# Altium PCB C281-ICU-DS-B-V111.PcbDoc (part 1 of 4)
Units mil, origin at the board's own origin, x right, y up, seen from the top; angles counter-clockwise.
Board outline 9370.03 x 5995.03 mil, 2 copper layers (Top Layer, Bottom Layer); 468 components, 321 nets, 1241 pads, 808 vias.
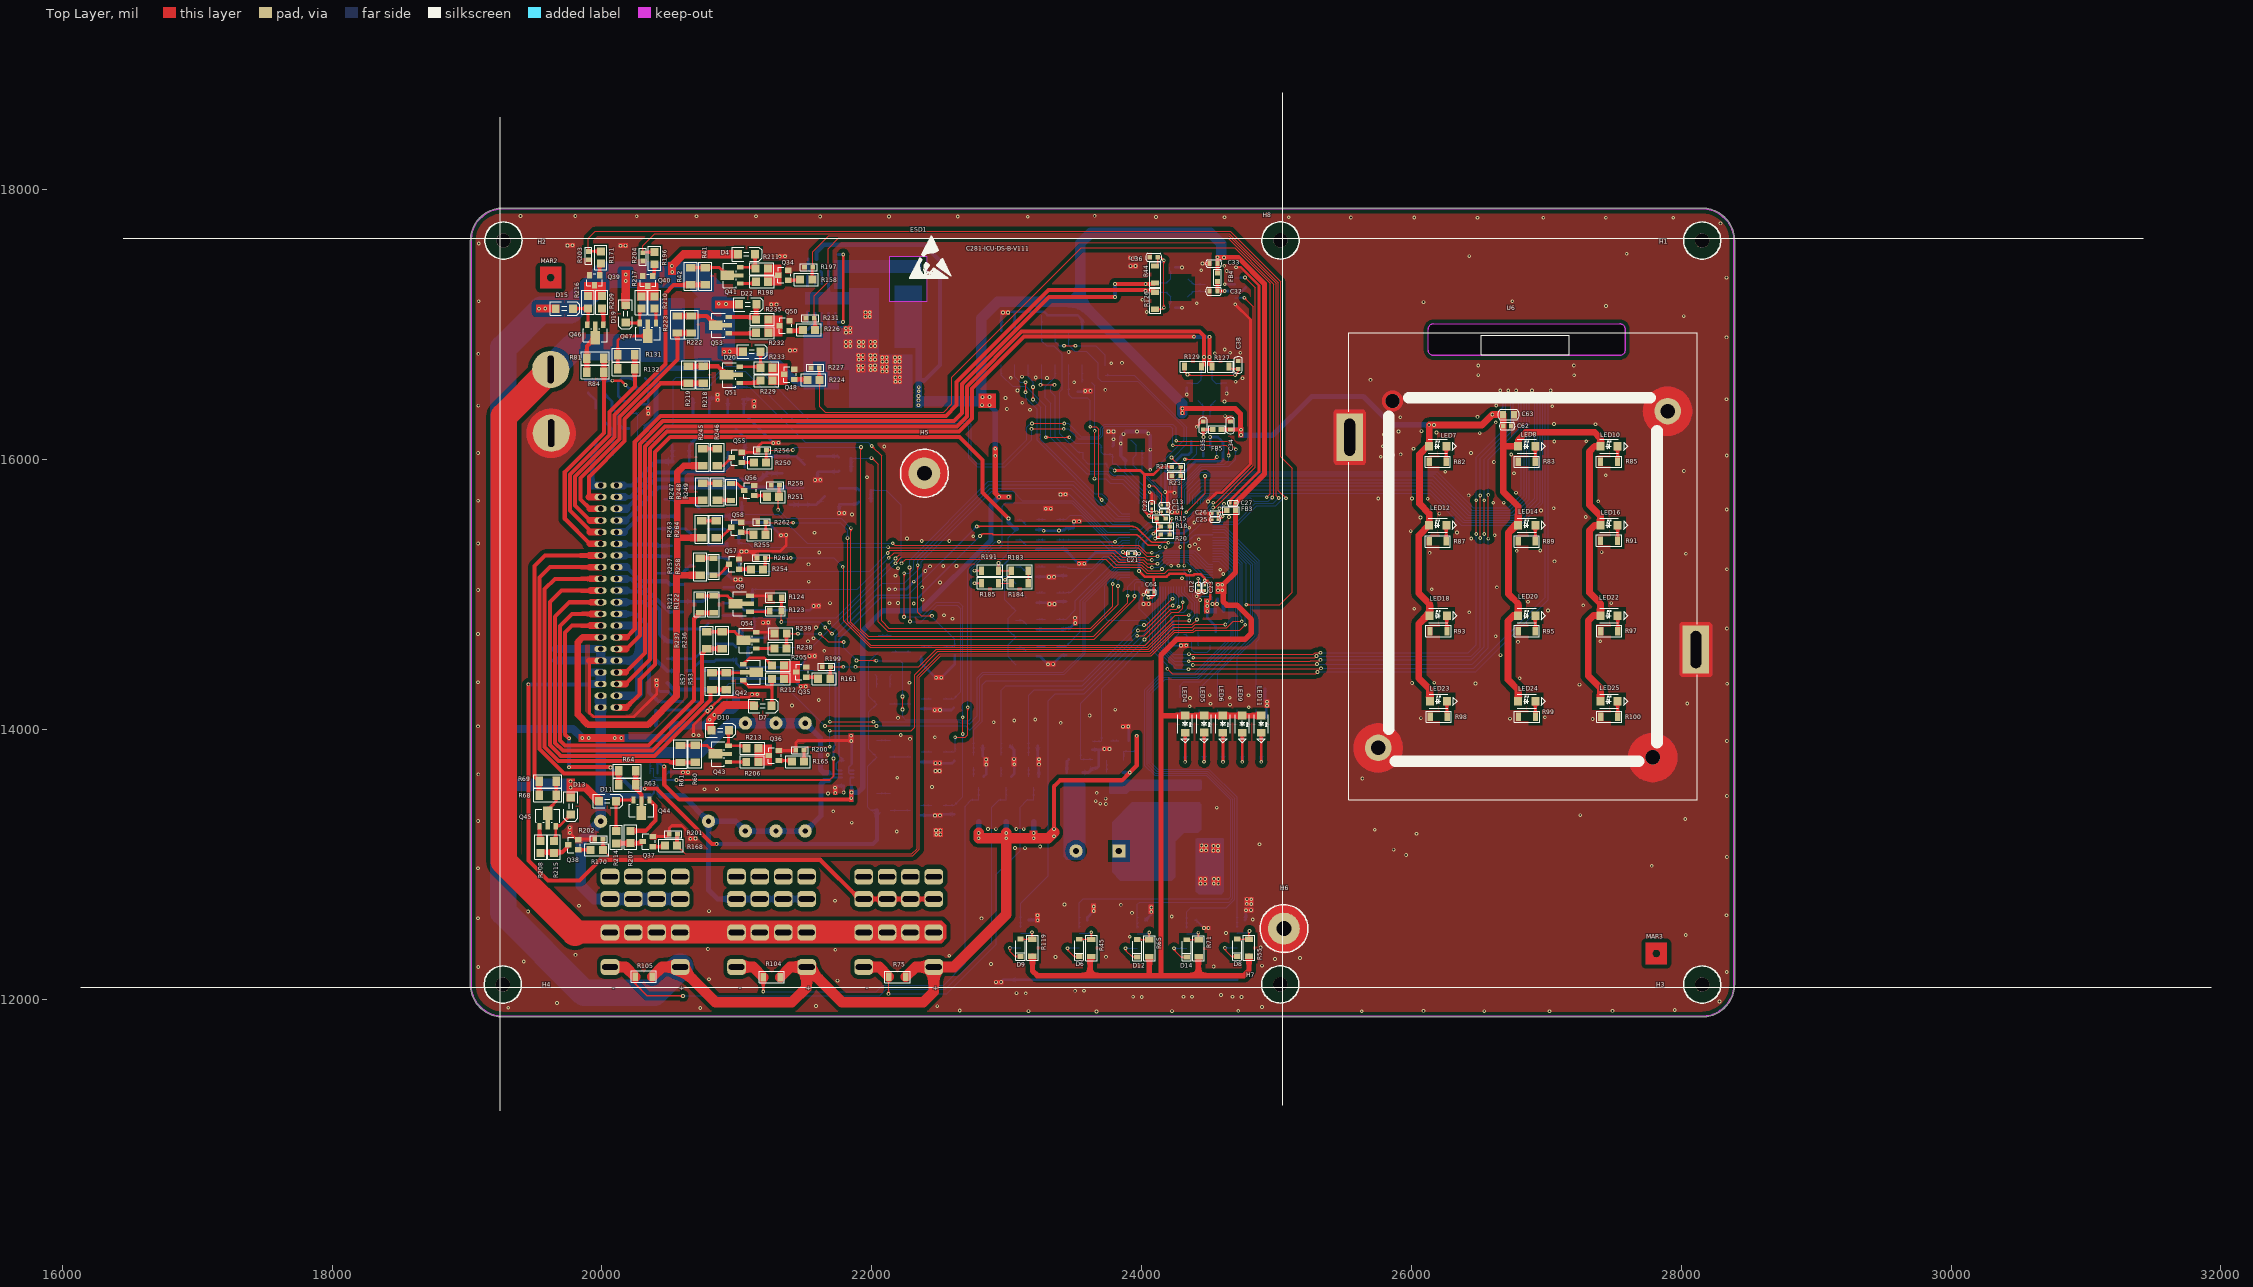
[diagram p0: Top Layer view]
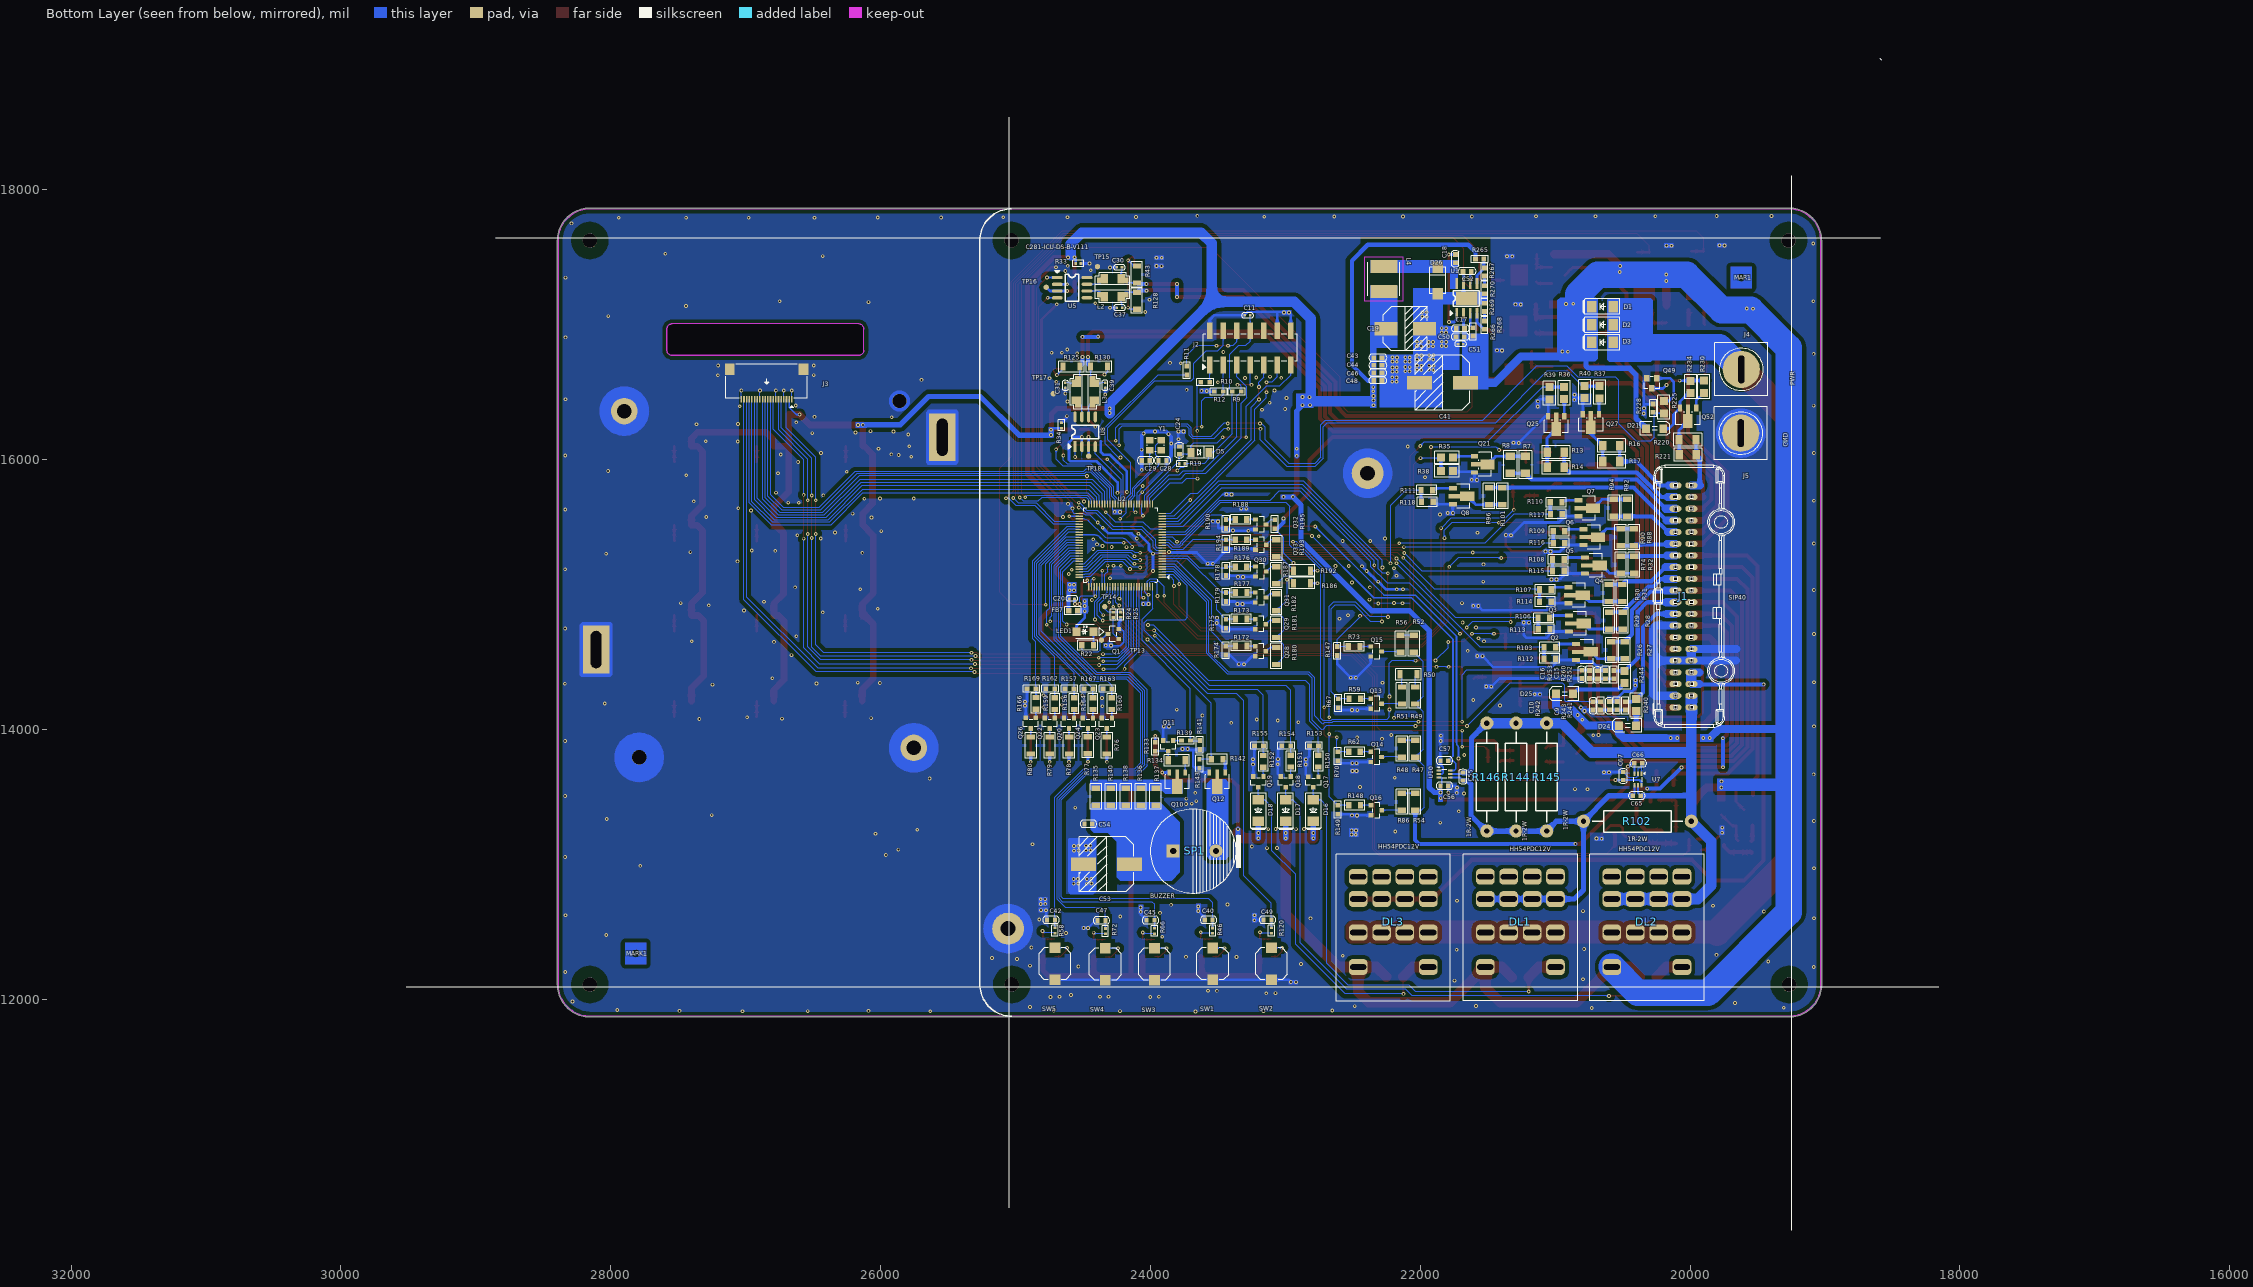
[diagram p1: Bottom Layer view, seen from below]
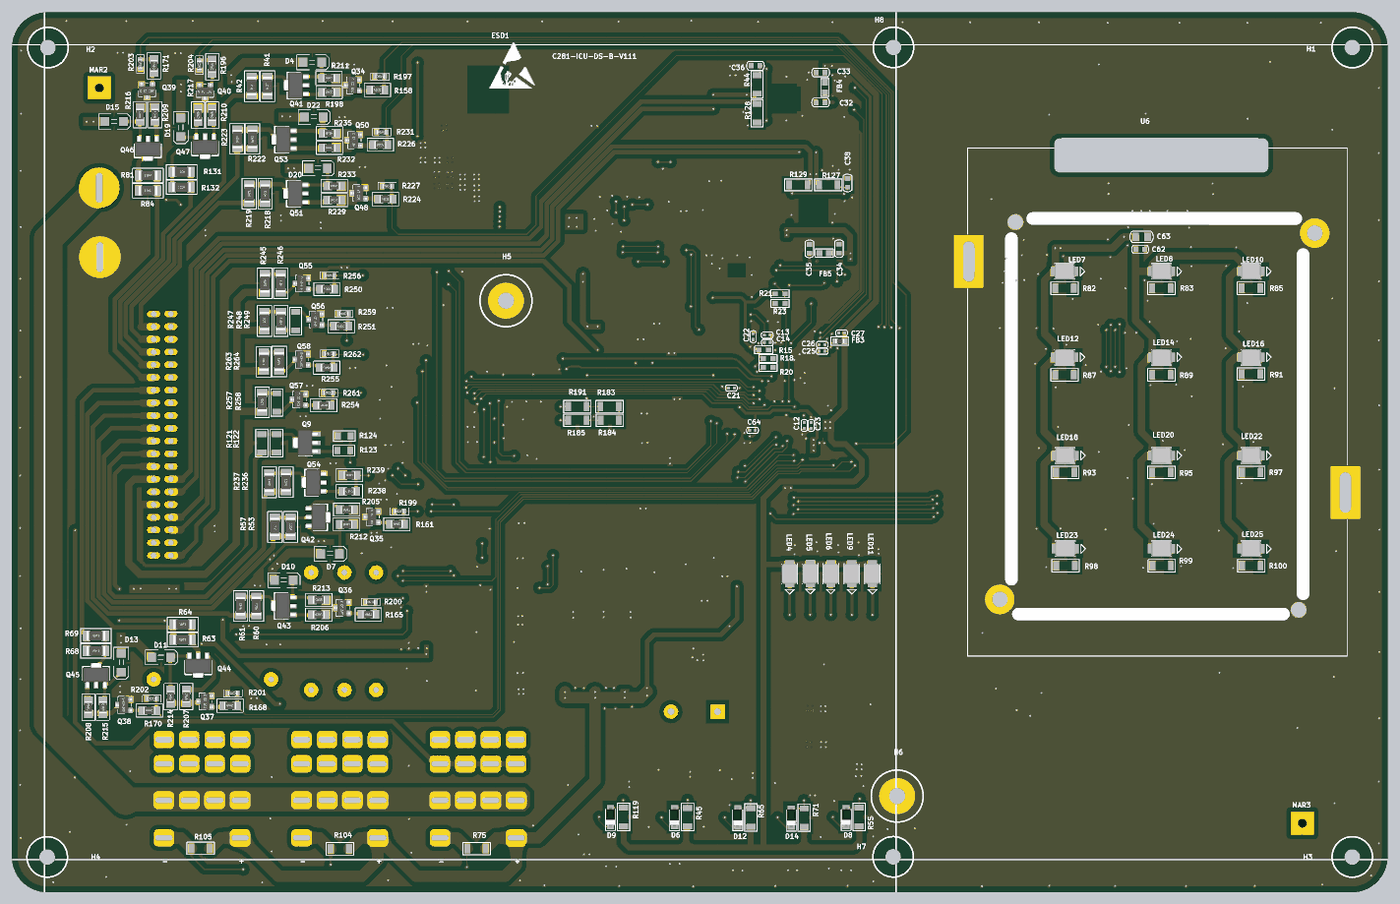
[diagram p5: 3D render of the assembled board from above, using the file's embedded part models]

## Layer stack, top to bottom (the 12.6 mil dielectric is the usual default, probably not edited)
Top Solder: solder mask 0.4, Solder Resist, Dk 3.5
Top Layer: signal copper 1.4
Dielectric 1: dielectric 12.6, FR-4, Dk 4.8
Bottom Layer: signal copper 1.4
Bottom Solder: solder mask 0.4, Solder Resist, Dk 3.5

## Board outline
19024.99,12110 19024.99,17625.73 cw(c19030,17625.73) 19025.72,17628.35 cw(c19265,17625.73) 19265,17865.01 28155.78,17865.01 28155.78,17865.02 cw(c28155.78,17625.78) 28395.01,17625.78 28395.01,12111 cw(c28390,12111) 28395.01,12111 cw(c28153.89,12111.11) 28153.78,11869.98 cw(c28153.78,11875) 28153.72,11869.99 19265,11869.99 cw(c19265,12110)
cut-out: 26124,16812.37 26124,16967.63 cw(c26163.37,16967.63) 26163.37,17007 27544.63,17007 cw(c27544.63,16967.63) 27584,16967.63 27584,16812.37 cw(c27544.63,16812.37) 27544.63,16773 26163.37,16773 cw(c26163.37,16812.37)

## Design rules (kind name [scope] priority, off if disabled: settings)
Clearance MIN [All] p1: gap=7.87 except(30: Arc-Poly Arc-Region Track-Poly Track-Region SMDPad-Poly SMDPad-Region THPad-Poly THPad-Region Via-Poly Via-Region Fill-Poly Fill-Region Poly-Poly Poly-Region Region-Region)
Clearance KEEP [OnLayer('Keep-Out Layer')] p2: gap=19.68
Clearance [All] p3: gap=11.81
ComponentClearance [All] p1 off: gap=10 collisioncheckmode=3 verticalgap=10 showdistances=FALSE
Height [All] p1 off: minheight=0 maxheight=1000 prefheight=500
HoleSize [All] p1: absolutevalues=TRUE maxlimit=787.4 minlimit=1 maxpercent=80.000 minpercent=20.000
MinimumSolderMaskSliver [All] p1 off: minsoldermaskwidth=10
PlaneConnect [All] p1: planeconnectstyle=Direct reliefexpansion=20 reliefentries=4 reliefconductorwidth=10 reliefairgap=10
PolygonConnect via [IsVia] p1: connectstyle=Direct reliefconductorwidth=10 reliefentries=4 polygonreliefangle="90 Angle" airgapwidth=10
PolygonConnect [All] p2: connectstyle=Direct reliefconductorwidth=10 reliefentries=4 polygonreliefangle="90 Angle" airgapwidth=10
RoutingVias [All] p1: holewidth=28 width=50 viastyle="Through Hole" minholewidth=28 minwidth=50 maxholewidth=28 maxwidth=50
SilkToSilkClearance [All] p1 off: silktosilkclearance=10
SilkToSolderMaskClearance [IsPad] p1 off: minsilkscreentomaskgap=10 clearancetoexposedcopper=TRUE
SolderMaskExpansion [All] p1: expansion=4
Width [All] p1: maxlimit=200 minlimit=1 preferedwidth=7.87
23 further rules are at their usual default settings.

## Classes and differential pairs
component class 07_Lcd-C281-ICU-DS-B-V111: C62 C63 J3 LED7 LED8 LED10 LED12 LED14 LED16 LED18 LED20 LED22 LED23 LED24 LED25 R82 R83 R85 R87 R89 R91 R93 R95 R97 R98 R99 R100 U6
component class 06_Peripheral-C281-ICU-DS-B-V111: C9 C10 C15 C16 C30 C31 C32 C33 C34 C35 C36 C37 C38 C39 C40 C42 C45 C47 C49 C53 C54 C55 C56 C57 C65 C66 C67 D4 D6 D7 D8 D9 D10 D11 D12 D13 D14 D15 D16 D17 D18 D19 D20 D21 D22 D24 D25 DL1 DL2 DL3 FB4 FB5 L2 L3 LED4 LED5 LED6 LED9 LED11 Q2 Q3 Q4 Q5 Q6 Q7 Q8 Q9 Q10 Q11 Q12 Q13 Q14 Q15 Q16 Q17 Q18 Q19 Q20 Q21 Q22 Q23 Q24 Q25 Q26 Q27 Q28 Q29 Q30 Q31 Q32 Q33 Q34 Q35 Q36 Q37 Q38 Q39 Q40 Q41 Q42 Q43 Q44 Q45 Q46 Q47 Q48 Q49 Q50 Q51 Q52 Q53 Q54 Q55 Q56 Q57 Q58 R7 R8 R13 R14 R16 R17 R26 R27 R28 R29 R30 R31 R32 R33 R34 R35 R36 R37 R38 R39 R40 R41 R42 R43 R44 R45 R46 R47 R48 R49 R50 R51 R52 R53 R54 R55 R56 R57 R58 R59 R60 R61 R62 R63 R64 R65 R66 R67 R68 R69 R70 R71 R72 R73 R74 R75 R76 R77 R78 R79 R80 R81 R84 R86 R88 R90 R92 R94 R96 R101 R102 R103 R104 R105 R106 R107 R108 R109 R110 R111 R112 R113 R114 R115 R116 R117 R118 R119 R120 R121 R122 R123 R124 R125 R126 R127 R128 R129 R130 R131 R132 R133 R134 R135 R136 R137 R138 R139 R140 R141 R142 R143 R144 R145 R146 R147 R148 R149 R150 R151 R152 R153 R154 R155 R156 R157 R158 R159 R160 R161 R162 R163 R164 R165 R166 R167 R168 R169 R170 R171 R172 R173 R174 R175 R176 R177 R178 R179 R180 R181 R182 R183 R184 R185 R186 R187 R188 R189 R190 R191 R192 R193 R194 R195 R196 R197 R198 R199 R200 R201 R202 R203 R204 R205 R206 R207 R208 R209 R210 R211 R212 R213 R214 R215 R216 R217 R218 R219 R220 R221 R222 R223 R224 R225 R226 R227 R228 R229 R230 R231 R232 R233 R234 R235 R236 R237 R238 R239 R240 R241 R242 R243 R244 R245 R246 R247 R248 R249 R250 R251 R252 R253 R254 R255 R256 R257 R258 R259 R260 R261 R262 R263 R264 SP1 SW1 SW2 SW3 SW4 SW5 TP15 TP16 TP17 TP18 U5 U7 U8 U10
component class 05_Controller-C281-ICU-DS-B-V111: C11 C12 C13 C14 C20 C21 C22 C23 C24 C25 C26 C27 C28 C29 C64 D5 FB3 FB7 J2 LED1 Q1 R9 R10 R11 R12 R15 R18 R19 R20 R21 R22 R23 R24 R25 TP13 TP14 U2 Y1
component class 04_Power-C281-ICU-DS-B-V111: C17 C18 C19 C41 C43 C44 C46 C48 C50 C51 C52 D26 L4 R265 R266 R267 R268 R269 R270 U1
component class 03_Connect-C281-ICU-DS-B-V111: D1 D2 D3 ESD1 H1 H2 H3 H4 H5 H6 H7 H8 J1 J4 J5 MAR1 MAR2 MAR3 MARK1

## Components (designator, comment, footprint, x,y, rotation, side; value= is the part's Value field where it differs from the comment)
C9 "103" C0603#1 20597.75,14177.23 r90 bottom
C10 "103" C0603#1 20719,14176 r270 bottom
C11 "104-25V" C0402-YAGEO 23280,17070 r0 bottom
C12 "104-25V" C0402-YAGEO 24421.69,15050.32 r90 top
C13 "104-25V" C0402-YAGEO 24169.53,15665 r180 top
C14 "104-25V" C0402-YAGEO 24169.84,15615 r180 top
C15 "103" C0603#1 20686,14405.61 r90 bottom
C16 "103" C0603#1 20803,14409.45 r270 bottom
C17 "105-50V" C0603#1 21702.39,16972.64 r180 bottom
C18 "104" C0603#1 21739.39,17490.11 r90 bottom
C19 "470uF-16V" CUT80102 22110.68,16971.11 r180 bottom locked
C20 "104-25V" C0402-YAGEO 24582.31,14971 r180 bottom
C21 "104-25V" C0402-YAGEO 23925.31,15305 r180 top
C22 "104-25V" C0402-YAGEO 24075,15655.32 r90 top
C23 "104-25V" C0402-YAGEO 24468.94,15050.32 r270 top
C24 "104" C0603-YAGEO 23785,16069.53 r90 bottom
C25 "104-25V" C0402-YAGEO 24544,15556 r180 top
C26 "106-10V" C0402-YAGEO 24544,15601.22 r180 top
C27 "106-10V" C0402-YAGEO 24676.31,15679 r180 top
C28 "10pF" C0603#2 23909.53,15995 r180 bottom
C29 "10pF" C0603#2 24035,15995 r0 bottom
C30 "47pF" C0402-YAGEO 24229.78,17425.68 r0 bottom
C31 "47pF" C0402-YAGEO 24630.48,16551.24 r270 bottom
C32 "106-16V" C0603-YAGEO 24533.57,17250.68 r180 top
C33 "106-16V" C0603-YAGEO 24533.57,17454.68 r180 top
C34 "106-16V" C0603-YAGEO 24658.48,16254.46 r90 top
C35 "106-16V" C0603-YAGEO 24457.48,16253.46 r90 top
C36 "104" C0603-YAGEO 24089.57,17500.68 r180 top
C37 "47pF" C0402-YAGEO 24228.78,17126.68 r0 bottom
C38 "104" C0603-YAGEO 24716.48,16702.46 r90 top
C39 "47pF" C0402-YAGEO 24335.32,16551.97 r270 bottom
C40 "104" C0603#2 23568.35,12587.99 r0 bottom
C41 "470uF-35V" CUT100102 21834.67,16570.78 r0 bottom locked
C42 "104" C0603#2 24736.9,12588.99 r0 bottom
C43 "106-16V" C0603#1 22313.45,16756.11 r0 bottom
C44 "106-16V" C0603#1 22313.45,16700.11 r0 bottom
C45 "104" C0603#2 23998.71,12585.99 r0 bottom
C46 "105-50V" C0603#1 22314.45,16644.11 r0 bottom
C47 "104" C0603#2 24362.88,12584.99 r0 bottom
C48 "104" C0603#1 22314.45,16587.11 r0 bottom
C49 "104" C0603#2 23131.82,12588.99 r0 bottom
C50 "105-50V" C0603#1 21703.39,16912.11 r180 bottom
C51 "102-50V" C0402 21698.74,16856.13 r180 bottom
C52 "103" C0603#1 21652.39,17396.11 r180 bottom
C53 "470uF-35V" CUT100102 24325.23,13001.23 r0 bottom
C54 "104" C0603#2 24459.72,13301 r0 bottom
C55 "104" C0603#2 21683.07,13651.57 r90 bottom
C56 "104" C0603#2 21820.87,13582.68 r180 bottom
C57 "103" C0603#2 21820.87,13769.68 r0 bottom
C62 "104" C0603#2 26710,16250 r0 top
C63 "106" C0805 26720,16335 r0 top
C64 "104-25V" C0402-YAGEO 24069,15017 r180 top
C65 "104" C0603#2 20395,13510 r180 bottom
C66 "104" C0603#2 20383.86,13750 r180 bottom
C67 "103" C0603#2 20495,13655.53 r90 bottom
D1 "M7" DO-214AC 20650.28,17135 r180 bottom
D2 "M7" DO-214AC 20650,17000 r180 bottom
D3 "M7" DO-214AC 20650,16870 r180 bottom
D4 "1N4148WHE3" SOD-123#1 21071.56,17524 r180 top
D5 "4148" 4148-A 23633.07,16055 r0 bottom
D6 "1N4148WHE3-TP" SOD-123#2 23538.83,12381.3 r270 top
D7 "1N4148WHE3" SOD-123#1 21192.12,14175 r180 top
D8 "1N4148WHE3-TP" SOD-123#2 24707.37,12382.3 r270 top
D9 "1N4148WHE3-TP" SOD-123#2 23102.29,12382.3 r270 top
D10 "1N4148WHE3" SOD-123#1 20876.36,13996 r180 top
D11 "1N4148WHE3" SOD-123#1 20040.5,13470 r180 top
D12 "1N4148WHE3-TP" SOD-123#2 23969.18,12379.3 r270 top
D13 "1N4148WHE3" SOD-123#1 19769,13433 r90 top
D14 "1N4148WHE3-TP" SOD-123#2 24333.35,12378.3 r270 top
D15 "1N4148WHE3" SOD-123#1 19721.12,17121 r180 top
D16 "M7" DO-214AC 22792.07,13398.79 r90 bottom
D17 "M7" DO-214AC 22997,13398.79 r90 bottom
D18 "M7" DO-214AC 23199.75,13398.79 r90 bottom
D19 "1N4148WHE3" SOD-123#1 20174.55,17081.56 r90 top
D20 "1N4148WHE3" SOD-123#1 21110,16802 r180 top
D21 "1N4148WHE3" SOD-123#1 20262,16231 r0 bottom
D22 "1N4148WHE3" SOD-123#1 21081,17151 r180 top
D24 "1N4148WHE3-TP" SOD-123#1 20462.56,14030 r180 bottom
D25 "1N4148WHE3-TP" SOD-123#1 20929.56,14264.56 r180 bottom
D26 "SS36" DO-214AB 21870.39,17329.11 r270 bottom
DL1 "HH54PDC12V" HH54PDC12V 21257.15,12531.77 r180 bottom locked
DL2 "HH54PDC12V" HH54PDC12V 20319.45,12531.77 r180 bottom locked
DL3 "HH54PDC12V" HH54PDC12V 22199.92,12531.42 r180 bottom locked
ESD1 "ESD防静电标识" ESD 22437,17467 r0 top
FB3 "1000@100MHz" BLM18PG600SH1 24664,15624.84 r0 top
FB4 "1000@100MHz" BLM18PG600SH1 24563.09,17352.64 r90 top
FB5 "1000@100MHz" BLM18PG600SH1 24558.48,16223.93 r0 top
FB7 "1000@100MHz" BLM18PG600SH1 24572,14880.87 r180 bottom
H1 "钉孔M2.5*12 - SU2" "钉孔M2.5*12 - SU2" 28155,17625 r0 top
H2 "钉孔M2.5*12 - SU2" "钉孔M2.5*12 - SU2" 19270,17625 r0 top
H3 "钉孔M2.5*12 - SU2" "钉孔M2.5*12 - SU2" 28155,12110 r0 top
H4 "钉孔M2.5*12 - SU2" "钉孔M2.5*12 - SU2" 19265,12110 r0 top
H5 "钉孔M2.5*12-BYD" "钉孔M2.5*12 - BYD" 22390,15900 r0 top
H6 "钉孔M2.5*12-BYD" "钉孔M2.5*12 - BYD" 25055,12525 r0 top locked
H7 "钉孔M2.5*12 - SU2" "钉孔M2.5*12 - SU2" 25027.59,12111.11 r0 top
H8 "钉孔M2.5*12 - SU2" "钉孔M2.5*12 - SU2" 25029.48,17625.78 r0 top
J1 "SIP40" 40P插座（白） 19989.89,14164.39 r270 bottom locked
J2 "JTAG_14" JTAG-14PIN 23260,16830 r180 bottom locked
J3 "101049-202060" 101049-202060 26845,16560 r0 bottom
J4 "BS105-4-DIP" DIP-4MM 19620,16670 r90 bottom
J5 "BS105-4-DIP" DIP-4MM 19624,16197 r90 bottom
L2 "ACT45C-101-2P-TL000" DLW43SH101XK2 24280.09,17275.68 r0 bottom
L3 "ACT45C-101-2P-TL000" DLW43SH101XK2 24482.95,16502.76 r270 bottom
L4 "6045EX-100M-H" VLS6045EX 22269.39,17339.11 r270 bottom
LED1 "R" LED 24485,14725 r0 bottom
LED4 "R" LED 24322.73,14040.03 r90 top
LED5 "R" LED 24463.2,14040.73 r90 top
LED6 "R" LED 24603.05,14040.03 r90 top
LED7 "W" LED 26195,16100 r180 top
LED8 "W" LED 26855,16100 r180 top
LED9 "G" LED 24745.84,14040.03 r90 top
LED10 "W" LED 27465,16100 r180 top
LED11 "R" LED 24886.43,14040.03 r90 top
LED12 "W" LED 26195,15515 r180 top
LED14 "W" LED 26855,15515 r180 top
LED16 "W" LED 27465,15515 r180 top
LED18 "W" LED 26198.56,14845 r180 top
LED20 "W" LED 26855,14845 r180 top
LED22 "W" LED 27465,14845 r180 top
LED23 "W" LED 26200,14210 r180 top
LED24 "W" LED 26855,14210 r180 top
LED25 "W" LED 27465,14210 r180 top
MAR1 "Mark" MARK 19620,17350 r180 bottom
MAR2 "Mark" MARK 19620,17350 r0 top
MAR3 "Mark" MARK 27815,12340 r0 top
MARK1 "Mark" MARK 27815,12340 r90 bottom
Q1 "MMS9013HE3-H" SOT-23#1 24274,14708 r90 bottom
Q2 "8050" SOT-89-3#1 20766.84,14575.53 r270 bottom
Q3 "8050" SOT-89-3#1 20818.76,14786.43 r270 bottom
Q4 "8050" SOT-89-3#1 20824.84,14996.28 r270 bottom
Q5 "8050" SOT-89-3#1 20700.51,15216 r270 bottom
Q6 "8050" SOT-89-3#1 20712.35,15426.63 r270 bottom
Q7 "8050" SOT-89-3#1 20749.2,15641 r270 bottom
Q8 "8050" SOT-89-3#1 21680.87,15728.89 r270 bottom
Q9 "8050" SOT-89-3#1 21020.31,14932.02 r90 top
Q10 "PBSS5250X" SOT-89 23801,13613.43 r0 bottom
Q11 "BC817-40-AU" SOT-23#1 23867.93,13879.18 r0 bottom
Q12 "PBSS4250X" SOT-89 23504.43,13613.43 r0 bottom
Q13 "BC817-40-AU" SOT-23#1 22326.77,14191.34 r270 bottom
Q14 "BC817-40-AU" SOT-23#1 22326.77,13797.64 r270 bottom
Q15 "BC817-40-AU" SOT-23#1 22326.77,14578.35 r270 bottom
Q16 "BC817-40-AU" SOT-23#1 22324.41,13401.57 r270 bottom
Q17 "BC817-40-AU" SOT-23#1 22792.07,13611.21 r0 bottom
Q18 "BC817-40-AU" SOT-23#1 22997,13612 r0 bottom
Q19 "BC817-40-AU" SOT-23#1 23199.75,13612 r0 bottom
Q20 "BC817-40-AU" SOT-23#1 24603.05,14047.23 r0 bottom
Q21 "8050" SOT-89-3#2 21549.55,15966.11 r270 bottom
Q22 "BC817-40-AU" SOT-23#1 24745.84,14047.23 r0 bottom
Q23 "BC817-40-AU" SOT-23#1 24322.73,14047.23 r0 bottom
Q24 "BC817-40-AU" SOT-23#1 24463.2,14047.23 r0 bottom
Q25 "8050" SOT-89-3#2 20992,16275.16 r0 bottom
Q26 "BC817-40-AU" SOT-23#1 24886.43,14047.67 r0 bottom
Q27 "8050" SOT-89-3#2 20735.04,16288.49 r0 bottom
Q28 "BC817-40-AU" SOT-23#1 23183.63,14580.91 r270 bottom
Q29 "BC817-40-AU" SOT-23#1 23183.63,14781.1 r270 bottom
Q30 "BC817-40-AU" SOT-23#1 23180.63,15171.26 r270 bottom
Q31 "BC817-40-AU" SOT-23#1 23182.63,14978.7 r270 bottom
Q32 "BC817-40-AU" SOT-23#1 23181.69,15519.78 r270 bottom
Q33 "BC817-40-AU" SOT-23#1 23180.63,15369.6 r270 bottom
Q34 "BC817-40-AU" SOT-23#2 21343.98,17367.92 r90 top
Q35 "BC817-40-AU" SOT-23#2 21476.78,14426.51 r90 top
Q36 "BC817-40-AU" SOT-23#2 21273.42,13807.67 r90 top
Q37 "BC817-40-AU" SOT-23#2 20340,13170 r90 top
Q38 "BC817-40-AU" SOT-23#2 19786.84,13146 r90 top
Q39 "BC817-40-AU" SOT-23#2 19944.99,17329.92 r180 top
Q40 "BC817-40-AU" SOT-23#2 20340,17325 r180 top
Q41 "8550" SOT-89-3#2 20976.16,17366.53 r90 top
Q42 "8550" SOT-89-3#2 21096,14425 r270 top
Q43 "8550" SOT-89-3#2 20889.26,13819.67 r90 top
Q44 "8550" SOT-89-3#2 20293.25,13430.16 r180 top
Q45 "8550" SOT-89-3#2 19597.76,13332.03 r0 top
Q46 "8550" SOT-89-3#2 19950.25,16952.16 r180 top
Q47 "8550" SOT-89-3#2 20340.25,16965.62 r180 top
Q48 "BC817-40-AU" SOT-23#2 21387.5,16632.84 r90 top
Q49 "BC817-40-AU" SOT-23#2 20284,16566 r0 bottom
Q50 "BC817-40-AU" SOT-23#2 21352.7,16993.85 r90 top
Q51 "8550" SOT-89-3#2 20972.37,16629.25 r90 top
Q52 "8550" SOT-89-3#2 20014.75,16335.16 r0 bottom
Q53 "8550" SOT-89-3#2 20891.76,16997.35 r90 top
Q54 "8050" SOT-89-3#2 21096.16,14660.75 r90 top
Q55 "BC817-40-AU" SOT-23#2 20997.87,16017.1 r90 top
Q56 "BC817-40-AU" SOT-23#2 21091.37,15772.08 r90 top
Q57 "BC817-40-AU" SOT-23#2 20978.72,15226.6 r90 top
Q58 "BC817-40-AU" SOT-23#2 20996.66,15499.1 r90 top
R7 "30R" R1206#1 21222.02,15962.91 r270 bottom
R8 "30R" R1206#1 21334.02,15961.91 r270 bottom
R9 "4K7" R0603-YAGEO 23360,16505 r180 bottom
R10 "100R-1%" R0603#1 23593.46,16575 r180 bottom
R11 "0R" R0603-YAGEO 23730,16661.54 r270 bottom
R12 "10K-J" R0603-YAGEO 23493.46,16505 r0 bottom
R13 "30R" R1206#1 20996.5,16055.18 r180 bottom
R14 "30R" R1206#1 20995.5,15943.45 r180 bottom
R15 "0R" R0603#1 24145,15565 r0 top
R16 "30R" R1206#1 20584.99,16105.01 r180 bottom
R17 "30R" R1206#1 20584.99,15987.01 r180 bottom
R18 "NC" R0603#1 24175,15505.75 r180 top
R19 "10K" R0402-YAGEO 23765.31,15970 r180 bottom
R20 "100K-J" R0603-YAGEO 24175,15445.75 r0 top
R21 "NC" R0603#1 24257.36,15946.57 r180 top
R22 "330R" R0805-YAGEO 24465,14625 r180 bottom
R23 "10K-J" R0603-YAGEO 24257.36,15881.57 r0 top
R24 "1K" R0402-YAGEO 24275,14851 r90 bottom
R25 "10K" R0402-YAGEO 24220,14851.63 r90 bottom
R26 "30R" R1206#2 20583.67,14588.41 r90 bottom
R27 "30R" R1206#2 20485.25,14588.41 r90 bottom
R28 "30R" R1206#2 20500.1,14807.81 r90 bottom
R29 "30R" R1206#2 20598.53,14807.81 r90 bottom
R30 "30R" R1206#2 20602.25,15012.66 r90 bottom
R31 "30R" R1206#2 20503.82,15012.66 r90 bottom
R32 "30R" R1206#2 20415.1,15222 r90 bottom
R33 "100K-J" R0402-YAGEO 24533.57,17454.68 r180 bottom
R34 "100K-J" R0402-YAGEO 24658.48,16254.46 r90 bottom
R35 "3K3" R0805#1 21801.39,16016.86 r0 bottom
R36 "3K3" R0805#1 20933.04,16493.99 r90 bottom
R37 "3K3" R0805#1 20669.97,16500.08 r90 bottom
R38 "10K" R0805#1 21801.39,15916.86 r0 bottom
R39 "10K" R0805#1 21042.04,16492.99 r90 bottom
R40 "10K" R0805#1 20781.63,16502.08 r90 bottom
R41 "30R" R1206#1 20765.23,17361.52 r270 top
R42 "30R" R1206#1 20658.3,17361.52 r270 top
R43 "1K2-J" R1206-YAGEO 24100.09,17373.67 r270 bottom
R44 "1K2-J" R1206-YAGEO 24100.09,17373.67 r270 top
R45 "1K2" R1206#2 23627.41,12381.3 r270 top
R46 "33K" R0402#1 23538.83,12509.25 r90 bottom
R47 "150R" R1206#2 22037.4,13858.27 r90 bottom
R48 "150R" R1206#2 22135.83,13858.27 r270 bottom
R49 "220R" R1206#2 22037.4,14251.97 r90 bottom
R50 "220R" R1206#2 22086.61,14409.45 r0 bottom
R51 "10R" R1206-YAGEO 22135.83,14251.97 r270 bottom
R52 "150R" R1206#2 22047.24,14635.83 r90 bottom
R53 "30R" R1206#1 20922.22,14358.76 r270 top
R54 "30R" R1206#2 22037.4,13464.57 r90 bottom
R55 "1K2" R1206#2 24795.95,12382.3 r270 top
R56 "10R" R1206-YAGEO 22145.67,14635.83 r270 bottom
R57 "30R" R1206#1 20815.79,14358.76 r270 top
R58 "33K" R0402#2 24707.37,12510.25 r90 bottom
R59 "3K3" R0805#2 22484.66,14228.74 r180 bottom
R60 "30R" R1206#1 20690,13819.69 r270 top
R61 "30R" R1206#1 20582,13819.19 r270 top
R62 "3K3" R0805#2 22486.63,13835.04 r180 bottom
R63 "30R" R1206#1 20187,13590.5 r180 top
R64 "30R" R1206#1 20187,13693.93 r180 top
R65 "1K2" R1206#2 24057.76,12379.3 r270 top
R66 "33K" R0402#1 23969.18,12507.25 r90 bottom
R67 "10K" R0603#1 22608,14195.54 r90 bottom
R68 "30R" R1206#1 19597.03,13514.29 r180 top
R69 "30R" R1206#1 19597.03,13617.72 r180 top
R70 "10K" R0603#1 22611.98,13801.57 r90 bottom
R71 "1K2" R1206#2 24421.94,12378.3 r270 top
R72 "33K" R0402#1 24333.35,12506.25 r90 bottom
R73 "3K3" R0805#2 22489.31,14615.75 r180 bottom
R74 "30R" R1206#2 20513.53,15222 r90 bottom
R75 "1K5" R1206#2 22189.76,12167.37 r0 top
R76 "330R" R1206#2 24322.73,13882.55 r90 bottom
R77 "330R" R1206#2 24463.2,13883.25 r90 bottom
R78 "150R" R1206#2 24603.05,13881.98 r90 bottom
R79 "150R" R1206#2 24745.84,13882.55 r90 bottom
R80 "330R" R1206#2 24886.43,13882.55 r90 bottom
R81 "30R" R1206#1 19950.96,16753.05 r0 top
R82 "330R" R1206#2 26195,15985 r180 top
R83 "330R" R1206#2 26855,15985 r180 top
R84 "30R" R1206#1 19950.96,16649.62 r0 top
R85 "330R" R1206#2 27465,15985 r180 top
R86 "30R" R1206#2 22135.83,13464.57 r270 bottom
R87 "330R" R1206#2 26195,15395 r180 top
R88 "30R" R1206#2 20416.72,15425.66 r270 bottom
R89 "330R" R1206#2 26855,15395 r180 top
R90 "30R" R1206#2 20515.15,15425.66 r270 bottom
R91 "330R" R1206#2 27465,15400 r180 top
R92 "30R" R1206#2 20465.9,15643.51 r270 bottom
R93 "330R" R1206#2 26200,14730 r180 top
R94 "30R" R1206#2 20564.32,15643.51 r270 bottom
R95 "330R" R1206#2 26855,14730 r180 top
R96 "30R" R1206#2 21489.85,15730.57 r90 bottom
R97 "330R" R1206#2 27467.01,14730 r180 top
R98 "330R" R1206#2 26202.01,14095 r180 top
R99 "330R" R1206#2 26857.01,14095 r180 top
R100 "330R" R1206#2 27467.01,14095 r180 top
R101 "30R" R1206#2 21391.43,15730.57 r90 bottom
R102 "1R-2W" 2WR 19990,13320 r180 bottom locked
R103 "3K3" R0805#2 21039.31,14610.11 r0 bottom
R104 "1K5" R1206#2 21258.76,12165.37 r0 top
R105 "1K5" R1206#2 20309.61,12168.37 r0 top
R106 "3K3" R0805#2 21083.31,14827.73 r0 bottom
R107 "3K3" R0805#2 21072.31,15038.28 r0 bottom
R108 "3K3" R0805#2 20975.82,15260.12 r0 bottom
R109 "3K3" R0805#2 20970.82,15469.94 r0 bottom
R110 "3K3" R0805#2 20992.67,15684.31 r0 bottom
R111 "3K3" R0805#2 21950.35,15774.2 r0 bottom
R112 "10K" R0805#2 21039.69,14525.27 r0 bottom
R113 "10K" R0805#2 21081,14744.4 r0 bottom
R114 "10K" R0805#2 21073,14947.53 r0 bottom
R115 "10K" R0805#2 20975.82,15175.54 r0 bottom
R116 "10K" R0805#2 20970.82,15382 r0 bottom
R117 "10K" R0805#2 20991,15597 r0 bottom
R118 "10K" R0805#2 21947.06,15688 r0 bottom
R119 "1K2" R1206#2 23190.87,12382.3 r270 top
R120 "33K" R0402#1 23102.29,12510.25 r90 bottom
R121 "30R" R1206#2 20726.86,14927.99 r270 top
R122 "30R" R1206#2 20827.2,14927.99 r270 top
R123 "3K3" R0805#2 21286.49,14879.23 r0 top
R124 "10K" R0805#2 21288.49,14978.11 r0 top
R125 "1K2-J" R1206-YAGEO 24585.32,16689.76 r180 bottom
R126 "1K2-J" R1206-YAGEO 24100.09,17177.69 r90 top
R127 "1K2-J" R1206-YAGEO 24585.32,16689.76 r180 top
R128 "1K2-J" R1206-YAGEO 24100.09,17177.69 r90 bottom
R129 "1K2-J" R1206-YAGEO 24380.59,16689.76 r0 top
R130 "1K2-J" R1206-YAGEO 24380.59,16689.76 r0 bottom
R131 "30R" R1206#1 20180.25,16777.12 r0 top
R132 "30R" R1206#1 20180.25,16673.69 r0 top
R133 "NC" R0603#1 23963.99,13873.28 r270 bottom
R134 "1K2-J" R1206#2 23804.94,13770.91 r180 bottom
R135 "30R" R1206#2 24403.26,13503.2 r270 bottom
R136 "30R" R1206#2 24071.61,13503.2 r270 bottom
R137 "30R" R1206#2 23961.06,13503.2 r270 bottom
R138 "30R" R1206#2 24182.16,13503.2 r270 bottom
R139 "10K" R0603#1 23736.67,13918.91 r0 bottom
R140 "NC" R1206#2 24292.71,13503.2 r270 bottom
R141 "NC" R0603#1 23633.68,13885.09 r90 bottom
R142 "3K3" R0805#2 23504.43,13779.98 r180 bottom
R143 "10K" R0603#1 23636.12,13746.52 r90 bottom
R144 "1R-2W" 2WR 21289.37,14048.03 r90 bottom locked
R145 "1R-2W" 2WR 21062.99,14048.03 r90 bottom locked
R146 "1R-2W" 2WR 21505.91,14048.03 r90 bottom locked
R147 "10K" R0603#1 22615,14582.28 r90 bottom
R148 "3K3" R0805#2 22486.4,13438.98 r180 bottom
R149 "10K" R0603#1 22612,13405.54 r90 bottom
R150 "3K3" R0805#2 22754.67,13765.53 r270 bottom
R151 "3K3" R0805#2 22959.08,13765.53 r270 bottom
R152 "3K3" R0805#2 23162.35,13764.54 r270 bottom
R153 "10K" R0603#1 22788.13,13879.7 r180 bottom
R154 "10K" R0603#1 22992.54,13879.7 r180 bottom
R155 "10K" R0603#1 23195.81,13879.7 r180 bottom
R156 "3K3" R0805#2 24565.45,14191.93 r270 bottom
R157 "10K" R0603#1 24599.11,14302.43 r180 bottom
R158 "3K3" R0805#1 21514,17336 r0 top
R159 "3K3" R0805#2 24708.44,14191.93 r270 bottom
R160 "3K3" R0805#2 24285.33,14191.93 r270 bottom
R161 "3K3" R0805#1 21647.05,14377 r0 top
R162 "10K" R0603#1 24741.9,14302.43 r180 bottom
R163 "10K" R0603#1 24318.79,14302.43 r180 bottom
R164 "3K3" R0805#2 24425.8,14191.93 r270 bottom
R165 "3K3" R0805#1 21452.69,13762 r0 top
R166 "3K3" R0805#2 24848.05,14193.99 r270 bottom
R167 "10K" R0603#1 24459.27,14302.43 r180 bottom
R168 "3K3" R0805#1 20511,13141 r0 top
R169 "10K" R0603#1 24881.51,14302.43 r180 bottom
R170 "3K3" R0805#1 19961,13108 r0 top
R171 "3K3" R0805#1 19992,17499.78 r90 top
R172 "3K3" R0805#2 23327.31,14619 r180 bottom
R173 "3K3" R0805#2 23327.31,14819 r180 bottom
R174 "10K" R0603#1 23441,14585.63 r90 bottom
R175 "10K" R0603#1 23440,14785.04 r90 bottom
R176 "3K3" R0805#2 23328.31,15208 r180 bottom
R177 "3K3" R0805#2 23327.31,15016 r180 bottom
R178 "10K" R0603#1 23440,15174.54 r90 bottom
R179 "10K" R0603#1 23440,14982.64 r90 bottom
R180 "0R" R1206#2 23067,14545.28 r90 bottom
R181 "1K" R1206#2 23067,14746.01 r90 bottom
R182 "2K2" R1206#2 23067,14944.17 r90 bottom
R183 "3K3" R1206#2 23095.99,15178 r0 top
R184 "150R" R1206#2 23096.99,15085 r180 top
R185 "150R" R1206#2 22876,15085 r180 top
R186 "150R" R1206#2 22876,15085 r0 bottom
R187 "150R" R1206#2 23066,15143.58 r90 bottom
R188 "3K3" R0805#2 23328.69,15557.19 r180 bottom
R189 "3K3" R0805#2 23328.31,15407 r180 bottom
R190 "10K" R0603#1 23440,15524.54 r90 bottom
R191 "3K3" R1206#2 22876,15178 r180 top
R192 "3K3" R1206#2 22876,15178 r0 bottom
R193 "200R-J" R1206#2 23066,15344.01 r90 bottom
R194 "10K" R0603#1 23440,15373.54 r90 bottom
R195 "15K" R0603#1 23078,15521.54 r90 bottom
R196 "3K3" R0805#1 20389,17494 r90 top
R197 "10K" R0603#2 21531.69,17427 r0 top
R198 "3K3" R0805#1 21185.36,17319.76 r0 top
R199 "10K" R0603#2 21663.73,14465 r0 top
R200 "10K" R0603#2 21467.37,13847 r0 top
R201 "10K" R0603#2 20528.69,13225 r0 top
R202 "10K" R0603#2 19977,13189 r0 top
R203 "10K" R0603#2 19900,17513 r90 top
R204 "10K" R0603#2 20302,17503.69 r90 top
R205 "3K3" R0805#1 21305,14476 r0 top
R206 "3K3" R0805#1 21114.42,13760.67 r0 top
R207 "3K3" R0805#1 20212,13203 r270 top
R208 "3K3" R0805#1 19545.01,13130.19 r270 top
R209 "3K3" R0805#1 19998.99,17167.61 r90 top
R210 "3K3" R0805#1 20389,17165 r90 top
R211 "10K" R0805#1 21184.36,17416.92 r0 top
R212 "10K" R0805#1 21304.86,14376 r0 top
R213 "10K" R0805#1 21115.17,13861.67 r0 top
R214 "10K" R0805#1 20106,13202 r270 top
R215 "10K" R0805#1 19644.01,13130.19 r270 top
R216 "10K" R0805#1 19896.99,17167.5 r90 top
R217 "10K" R0805#1 20292,17165 r90 top
R218 "30R" R1206#1 20749.5,16630 r270 top
R219 "30R" R1206#1 20640.5,16629.51 r270 top
R220 "30R" R1206#1 20019.01,16148.35 r180 bottom
R221 "30R" R1206#1 20017.01,16037.35 r180 bottom
R222 "30R" R1206#1 20663,17002.35 r270 top
R223 "30R" R1206#1 20559.57,17002.35 r270 top
R224 "3K3" R0805#1 21568,16592 r0 top
R225 "3K3" R0805#1 20194,16388.85 r270 bottom
R226 "3K3" R0805#1 21534,16962.35 r0 top
R227 "10K" R0603#2 21580.69,16681 r0 top
R228 "10K" R0603#2 20274,16382.05 r270 bottom
R229 "3K3" R0805#1 21219.98,16586.01 r0 top
R230 "3K3" R0805#1 19898,16541.4 r90 bottom
R231 "10K" R0603#2 21542.69,17049 r0 top
R232 "3K3" R0805#1 21187.73,16941.6 r0 top
R233 "10K" R0805#1 21220.31,16682.01 r0 top
R234 "10K" R0805#1 19996,16540.44 r90 bottom
R235 "10K" R0805#1 21187.73,17040.6 r0 top
R236 "30R" R1206#1 20891.89,14663.43 r270 top
R237 "30R" R1206#1 20777.43,14662.43 r270 top
R238 "3K3" R0805#1 21322.78,14601.26 r0 top
R239 "10K" R0805#1 21324.78,14711.26 r0 top
R240 "3K3" R0805#1 20399,14181.04 r270 bottom
R241 "10K" R0603#2 20479,14176 r90 bottom
R242 "10K" R0603#2 20663,14176 r270 bottom
R243 "10K" R0603#2 20542,14177 r270 bottom
R244 "3K3" R0805#1 20484.5,14389.61 r270 bottom
R245 "150R" R1206#1 20746.99,16018.61 r90 top
R246 "150R" R1206#1 20855.99,16019.6 r270 top
R247 "220R" R1206#1 20745.5,15761.59 r90 top
R248 "220R" R1206#1 20856.5,15761.59 r270 top
R249 "10R" R1206-YAGEO 20957.05,15761.58 r90 top
R250 "3K3" R0805#1 21171.5,15979.59 r180 top
R251 "3K3" R0805#1 21267.58,15725.57 r180 top
R252 "10K" R0603#2 20566,14407.61 r90 bottom
R253 "10K" R0603#2 20744.64,14408.61 r270 bottom
R254 "3K3" R0805#1 21148.78,15187.59 r180 top
R255 "3K3" R0805#1 21168.5,15443.92 r180 top
R256 "10K" R0603#2 21188.5,16071.59 r0 top
R257 "150R" R1206#1 20729.26,15207.61 r90 top
R258 "10R" R1206-YAGEO 20828.26,15206.61 r270 top
R259 "10K" R0603#2 21285.22,15811.57 r0 top
R260 "10K" R0603#2 20626,14407.75 r270 bottom
R261 "10K" R0603#2 21180,15272.07 r0 top
R262 "10K" R0603#2 21185.5,15538.59 r0 top
R263 "30R" R1206#1 20739.79,15484.51 r90 top
R264 "30R" R1206#1 20845.79,15486.04 r270 top
R265 "47K-J" R0603#2 21559.39,17487.65 r0 bottom
R266 "NC" R0603#2 21608.39,16947.8 r90 bottom
R267 "8.06K-J" R0603#2 21523.39,17392 r90 bottom
R268 "0R" R0603#2 21523.47,16997.35 r90 bottom
R269 "100K" R0603#2 21523.39,17130.11 r90 bottom
R270 "220R-J" R0603#2 21523.39,17260.11 r90 bottom
SP1 "BUZZER" FMQ(CN200) 23682.13,13099.65 r180 bottom
SW1 "按键1" SKPMAPE010 23538.83,12263.19 r90 bottom
SW2 "按键1" SKPMAPE010 23102.29,12264.19 r90 bottom
SW3 "按键1" SKPMAPE010 23969.18,12261.19 r90 bottom
SW4 "按键1" SKPMAPE010 24333.35,12260.19 r90 bottom
SW5 "按键1" SKPMAPE010 24707.37,12264.19 r90 bottom
TP13 "1.0测试点" TP1.0 24363,14663 r90 bottom
TP14 "1.0测试点" TP1.0 24338.11,14911 r90 bottom
TP15 "1.0测试点" TP1.0 24392.41,17431.68 r90 bottom
TP16 "1.0测试点" TP1.0 24772.09,17278.68 r0 bottom
TP17 "1.0测试点" TP1.0 24719,16489.54 r0 bottom
TP18 "1.0测试点" TP1.0 24457.48,16027 r0 bottom
U1 "JWH5123S" ESOP8 21654.39,17196.11 r180 bottom
U2 "R7F7016843" P-LFQFP100 24220,15365 r90 bottom locked
U5 "TJA1044GT" SO-8 24580.09,17275.68 r180 bottom
U6 "3.5 MONO_TFT" "3.5 MONO_TFT" 26825,15210 r180 top locked
U7 "INA214-Q1" INA214-Q1 20385,13630 r0 bottom locked
U8 "TJA1044GT" SO-8 24482.95,16207.48 r90 bottom
U10 "INA214-Q1" INA214-Q1 21820.87,13671.26 r270 bottom locked
Y1 "8M" Crystal3225 23961.69,16107.6 r180 bottom

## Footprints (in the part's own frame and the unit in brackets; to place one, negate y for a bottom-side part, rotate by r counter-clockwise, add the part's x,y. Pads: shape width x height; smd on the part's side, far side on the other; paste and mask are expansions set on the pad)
2WR [mm]
  round 2.5 hole 1: 1(0,0) 2(-20.32,0)
  Top Layer pour cut-out: -18.923,2.159 -18.923,-2.159 -1.27,-2.159 -1.27,2.159
  silkscreen extent -18.7,-2.03 -1.63,2.03, body extent -20.66,-2.5 0.34,2.5, height 5.1
"3.5 MONO_TFT" [mm]
  round 5 hole 2.7 mask+0.05: 1(-27.294,-29.226) 2(27.206,34.174)
  round 2.7 hole 2.7 mask+0.05: 3(-24.5,35.974) 4(24.508,-31.126)
  rect 5x9 hole 2 slot 7 at 90 deg mask+0.05: 5(-32.595,15.67) 6(32.581,-24.31)
  silkscreen extent -32.89,-43.97 32.8,43.97
40P插座（白） [mil]
  oval 45x90 hole 39.37: 1(0,0) 2(-86.62,0) 3(-173.23,0) 4(-259.84,0) 5(-346.46,0) 6(-433.07,0) 7(-519.69,0) 8(-606.3,0) 9(-692.92,0) 10(-779.53,0) 11(-866.14,0) 12(-952.76,0) 13(-1039.37,0) 14(-1125.98,0) 15(-1212.6,0) 16(-1299.21,0) 17(-1385.83,0) 18(-1472.44,0) 19(-1559.06,0) 20(-1645.67,0) 21(0,-118.11) 22(-86.61,-118.11) 23(-173.23,-118.11) 24(-259.84,-118.11) 25(-346.46,-118.11) 26(-433.07,-118.11) 27(-519.68,-118.11) 28(-606.3,-118.11) 29(-692.91,-118.11) 30(-779.52,-118.11) 31(-866.14,-118.11) 32(-952.75,-118.11) 33(-1039.37,-118.11) 34(-1125.98,-118.11) 35(-1212.6,-118.11) 36(-1299.21,-118.11) 37(-1385.83,-118.11) 38(-1472.44,-118.11) 39(-1559.05,-118.11) 40(-1645.67,-118.11)
  Top Layer pour cut-out: -1704,80 61,80 61,-186 -1704,-186
  Bottom Layer pour cut-out: -1704,80 61,80 61,-186 -1704,-186
  silkscreen extent -1795,-283 150,319
4148-A [mm] "取自《FE-3AD》"
  rect 1.3x1.7 smd paste+0 mask+0.05: 1(1.7,0) 2(-1.7,0)
  Top Layer pour cut-out: -1,0.9 -1,-0.9 1,-0.9 1,0.9
  silkscreen extent -2.63,-1.12 2.47,1.12, body extent -1.75,-0.78 1.75,0.82, height 1.6
101049-202060 [mm]
  rect 1.8x2.2 smd mask+0.05: 01(-6.95,-2.825) 02(6.95,-2.825)
  rect 0.3x1.3 smd mask+0.05: 1(-4.75,2.825) 2(-4.25,2.825) 3(-3.75,2.825) 4(-3.25,2.825) 5(-2.75,2.825) 6(-2.25,2.825) 7(-1.75,2.825) 8(-1.25,2.825) 9(-0.75,2.825) 10(-0.25,2.825) 11(0.25,2.825) 12(0.75,2.825) 13(1.25,2.825) 14(1.75,2.825) 15(2.25,2.825) 16(2.75,2.825) 17(3.25,2.825) 18(3.75,2.825) 19(4.25,2.825) 20(4.75,2.825)
  silkscreen extent -7.65,-3.8 7.65,4.43, body extent -7.65,-3.8 7.65,2.65, height 2.5
BLM18PG600SH1 [mm]
  rect 1x1 smd mask+0.05: 1(-0.812,0) 2(0.812,0)
  Top Layer pour cut-out: -0.3,0.5 0.3,0.5 0.3,-0.5 -0.3,-0.5
  silkscreen extent -1.55,-0.72 1.55,0.72, body extent -0.8,-0.4 0.8,0.4, height 0.38
C0402 [mm]
  rect 0.5x0.5 smd mask+0.05: 1(-0.55,0.025) 2(0.45,0.025)
  Top Layer pour cut-out: 0.2,0.275 -0.3,0.275 -0.3,-0.225 0.2,-0.225
  silkscreen extent -1.09,-0.5 0.99,0.55, body extent -0.55,-0.22 0.45,0.28, height 0.5
C0402-YAGEO [mm]
  rect 0.5x0.5 smd mask+0.05: 1(-0.5,0) 2(0.5,0)
  Top Layer pour cut-out: 0.25,0.25 -0.25,0.25 -0.25,-0.25 0.25,-0.25
  silkscreen extent -1.04,-0.53 1.04,0.53, body extent -0.5,-0.25 0.5,0.25, height 0.55
C0603#1 [mm]
  rect 0.9x0.9 smd: 1(-0.77,0) 2(0.77,0)
  silkscreen extent -1.62,-0.65 1.62,0.65, body extent -0.8,-0.4 0.8,0.4, height 0.6
C0603#2 [mm]
  rect 0.8x0.9 smd mask+0.05: 1(-0.75,0) 2(0.75,0)
  Top Layer pour cut-out: 0.35,0.45 -0.35,0.45 -0.35,-0.45 0.35,-0.45
  silkscreen extent -1.48,-0.72 1.48,0.72, body extent -0.8,-0.4 0.8,0.4, height 0.9
C0603-YAGEO [mm]
  rect 0.8x0.9 smd mask+0.05: 1(-0.75,0) 2(0.75,0)
  Top Layer pour cut-out: 0.35,0.45 -0.35,0.45 -0.35,-0.45 0.35,-0.45
  silkscreen extent -1.54,-0.75 1.54,0.75, body extent -0.8,-0.4 0.8,0.4, height 0.9
C0805 [mm]
  rect 1.15x1.4 smd mask+0.05: 1(-1.025,0) 2(1.025,0)
  Top Layer pour cut-out: 0.45,0.7 -0.45,0.7 -0.45,-0.7 0.45,-0.7
  silkscreen extent -2.03,-0.98 2.03,0.97, body extent -1,-0.63 1,0.63, height 1.45
Crystal3225 [mm]
  rect 1.4x1.2 smd mask+0.05: 1(-1.1,-0.95) 2(1.1,-0.95) 3(1.1,0.95) 4(-1.1,0.95)
  Multi-Layer pour cut-out: -1.6,-1.25 -1.6,1.25 1.6,1.25 1.6,-1.25
  silkscreen extent -1.6,-1.25 1.6,1.25, body extent -1.6,-1.25 1.6,1.25, height 0.77
CUT80102 [mm]
  rect 4.25x2.5 smd mask+0.05: 1(-3.625,0) 2(3.625,0)
  Top Layer pour cut-out: -1.475,4.15 1.475,4.15 1.475,-4.175 -1.475,-4.175
  silkscreen extent -4.15,-4.15 4.15,4.15, body extent -4.95,-4.15 4.95,4.15, height 10.2
CUT100102 [mm]
  rect 4.65x2.5 smd mask+0.05: 1(-4.325,0) 2(4.325,0)
  Top Layer pour cut-out: -1.975,-5.15 1.975,-5.15 1.975,5.15 -1.975,5.15
  silkscreen extent -5.15,-5.15 5.15,5.15, body extent -5.8,-5.15 5.8,5.15, height 10.2
DIP-4MM [mm]
  round 7 hole 1.2 slot 5.2 at 0 deg: 1(0,0)
  silkscreen extent -5,-5 5,5
DLW43SH101XK2 [mm]
  rect 1.35x1.1 smd mask+0.05: 1(-2.277,1.35) 2(2.277,1.35) 3(2.277,-1.35) 4(-2.277,-1.35)
  rect 1.4x1.8 smd mask+0.05: 1(-1.6,1.7) 2(1.6,1.7) 3(1.6,-1.7) 4(-1.6,-1.7)
  Multi-Layer pour cut-out: -2.3,2.6 -2.3,-2.6 2.3,-2.6 2.3,2.6
  Multi-Layer pour cut-out: -2.975,2.125 2.975,2.125 2.975,-2.125 -2.975,-2.125
  silkscreen extent -3.22,-2.82 3.22,2.82, body extent -2.98,-2.12 2.98,2.12, height 2.8
DO-214AB [mm]
  rect 2.2x2 smd: 1(2.493,0) 2(-2.493,0)
  Top Layer pour cut-out: 1.185,-0.993 1.185,1.039 -1.228,1.039 -1.228,-0.993
  silkscreen extent -2.49,-1.5 2.51,1.5, body extent -2.84,-1.19 2.64,1.6, height 2.24
DO-214AC [mm]
  rect 1.78x2.16 smd: 1(2.025,0) 2(-2.025,0)
  Top Layer pour cut-out: -1.125,1.075 -1.125,-1.075 1.125,-1.075 1.125,1.075
  silkscreen extent -3.57,-1.46 3.25,1.46, body extent -2.74,-1.4 2.74,1.4, height 2.29
ESD [mil]
  silkscreen extent -160,-121 151,194
ESOP8 [mm]
  rect 4x2.4 smd: 0(0,0)
  rect 0.51x2.03 smd: 1(-1.905,-2.794) 2(-0.635,-2.794) 3(0.635,-2.794) 4(1.905,-2.794) 5(1.905,2.794) 6(0.635,2.794) 7(-0.635,2.794) 8(-1.905,2.794)
  silkscreen extent -3.17,-3.29 2.31,1.4, body extent -2.51,-3.02 2.51,3.02, height 1.6
FMQ(CN200) [mm]
  rect 2.5x2.5 hole 1.2: 1(-3.8,0)
  round 2.5 hole 1.2: 2(4.273,0.02)
  Top Layer pour cut-out: -5.705,1.905 -1.895,1.905 -1.895,-1.905 -5.705,-1.905
  Bottom Layer pour cut-out: -5.705,1.905 -1.895,1.905 -1.895,-1.905 -5.705,-1.905
  silkscreen extent -8,-8 9.03,8, body extent -8,-8 8,8, height 14
HH54PDC12V [mm]
  rrect50% 3.5x3 hole 1 slot 3 at 0 deg mask+0.05: 1(6.6,9.6) 2(2.2,9.6) 3(-2.2,9.6) 4(-6.6,9.6) 5(6.6,5.4) 6(2.2,5.4) 7(-2.2,5.4) 8(-6.6,5.4) 9(6.6,-0.9) 10(2.2,-0.9) 11(-2.2,-0.9) 12(-6.6,-0.9) 13(6.6,-7.4) 14(-6.6,-7.4)
  silkscreen extent -10.75,-13.8 10.75,13.8, body extent -10.75,-13.8 10.75,13.8, height 34
INA214-Q1 [mm]
  rect 0.35x0.85 smd mask+0.05: 1(-0.65,-1.1) 2(0,-1.1) 3(0.65,-1.1) 4(0.65,1.1) 5(0,1.1) 6(-0.65,1.1)
  silkscreen extent -1.3,-1.35 0.82,0.45, body extent -0.97,-1.05 1.03,1.05, height 0.92
JTAG-14PIN [mm]
  rect 1.02x3.17 smd mask+0.05: 1(-7.62,-3.215) 2(-7.62,3.215) 3(-5.08,-3.215) 4(-5.08,3.215) 5(-2.54,-3.215) 6(-2.54,3.215) 7(0,-3.215) 8(0,3.215) 9(2.54,-3.215) 10(2.54,3.215) 11(5.08,-3.215) 12(5.08,3.215) 13(7.62,-3.215) 14(7.62,3.215)
  silkscreen extent -8.94,-4.17 8.89,2.5, body extent -8.89,-3.75 8.89,3.75, height 10.5
LED [mm] "取自《J11》(1206)"
  rect 1.5x1.6 smd: 1(1.615,0) 2(-1.615,0)
  Top Layer pour cut-out: -0.773,0.889 -0.773,-0.889 0.751,-0.889 0.751,0.889
  silkscreen extent -3.51,-1.35 1.75,1.35, body extent -1.75,-1.35 1.75,1.35, height 1.95
MARK [mil]
  Top Layer region: 0,-29.53 11.3,-27.28 20.88,-20.88 27.28,-11.3 29.53,0 29.53,0 27.28,11.3 20.88,20.88 11.3,27.28 0,29.53 0,29.53 0,78.74 78.74,78.74 78.74,-78.74 0,-78.74
  Top Layer region: -78.74,-78.74 -78.74,78.74 0,78.74 0,29.53 -11.3,27.28 -20.88,20.88 -27.28,11.3 -29.53,0 -29.53,0 -27.28,-11.3 -20.88,-20.88 -11.3,-27.28 0,-29.53 0,-29.53 0,-78.74
P-LFQFP100 [mm]
  rect 0.25x1.4 smd mask+0.05: 1(-6,-7.8) 2(-5.5,-7.8) 3(-5,-7.8) 4(-4.5,-7.8) 5(-4,-7.8) 6(-3.5,-7.8) 7(-3,-7.8) 8(-2.5,-7.8) 9(-2,-7.8) 10(-1.5,-7.8) 11(-1,-7.8) 12(-0.5,-7.8) 13(0,-7.8) 14(0.5,-7.8) 15(1,-7.8) 16(1.5,-7.8) 17(2,-7.8) 18(2.5,-7.8) 19(3,-7.8) 20(3.5,-7.8) 21(4,-7.8) 22(4.5,-7.8) 23(5,-7.8) 24(5.5,-7.8) 25(6,-7.8) 51(6,7.8) 52(5.5,7.8) 53(5,7.8) 54(4.5,7.8) 55(4,7.8) 56(3.5,7.8) 57(3,7.8) 58(2.5,7.8) 59(2,7.8) 60(1.5,7.8) 61(1,7.8) 62(0.5,7.8) 63(0,7.8) 64(-0.5,7.8) 65(-1,7.8) 66(-1.5,7.8) 67(-2,7.8) 68(-2.5,7.8) 69(-3,7.8) 70(-3.5,7.8) 71(-4,7.8) 72(-4.5,7.8) 73(-5,7.8) 74(-5.5,7.8) 75(-6,7.8)
  rect 1.4x0.25 smd mask+0.05: 26(7.8,-6) 27(7.8,-5.5) 28(7.8,-5) 29(7.8,-4.5) 30(7.8,-4) 31(7.8,-3.5) 32(7.8,-3) 33(7.8,-2.5) 34(7.8,-2) 35(7.8,-1.5) 36(7.8,-1) 37(7.8,-0.5) 38(7.8,0) 39(7.8,0.5) 40(7.8,1) 41(7.8,1.5) 42(7.8,2) 43(7.8,2.5) 44(7.8,3) 45(7.8,3.5) 46(7.8,4) 47(7.8,4.5) 48(7.8,5) 49(7.8,5.5) 50(7.8,6) 76(-7.8,6) 77(-7.8,5.5) 78(-7.8,5) 79(-7.8,4.5) 80(-7.8,4) 81(-7.8,3.5) 82(-7.8,3) 83(-7.8,2.5) 84(-7.8,2) 85(-7.8,1.5) 86(-7.8,1) 87(-7.8,0.5) 88(-7.8,0) 89(-7.8,-0.5) 90(-7.8,-1) 91(-7.8,-1.5) 92(-7.8,-2) 93(-7.8,-2.5) 94(-7.8,-3) 95(-7.8,-3.5) 96(-7.8,-4) 97(-7.8,-4.5) 98(-7.8,-5) 99(-7.8,-5.5) 100(-7.8,-6)
  silkscreen extent -7,-9.15 7,7, body extent -7.01,-7.01 6.98,6.98, height 1.7
R0402#1 [mm]
  rect 0.5x0.6 smd mask+0.05: 1(-0.5,0) 2(0.5,0)
  Top Layer pour cut-out: 0.25,0.3 -0.25,0.3 -0.25,-0.3 0.25,-0.3
  silkscreen extent -1.02,-0.58 1.02,0.58, body extent -0.5,-0.25 0.5,0.25, height 0.35
R0402#2 [mm]
  rect 0.5x0.6 smd mask+0.05: 1(-0.5,0) 2(0.5,0)
  silkscreen extent -1.02,-0.58 1.02,0.58, body extent -0.5,-0.25 0.5,0.25, height 0.35
R0402-YAGEO [mm]
  rect 0.5x0.6 smd mask+0.05: 1(-0.5,0) 2(0.5,0)
  Top Layer pour cut-out: 0.25,0.3 -0.25,0.3 -0.25,-0.3 0.25,-0.3
  silkscreen extent -1.02,-0.58 1.02,0.58, body extent -0.5,-0.25 0.5,0.25, height 0.35
R0603#1 [mm]
  rect 0.9x0.8 smd mask+0.05: 1(-0.85,0) 2(0.85,0)
  Top Layer pour cut-out: 0.4,0.4 -0.4,0.4 -0.4,-0.4 0.4,-0.4
  silkscreen extent -1.58,-0.67 1.58,0.67, body extent -0.8,-0.4 0.8,0.4, height 0.5
R0603#2 [mm]
  rect 0.9x0.9 smd: 1(-0.77,0) 2(0.77,0)
  silkscreen extent -1.58,-0.65 1.61,0.65, body extent -0.8,-0.4 0.8,0.4, height 0.45
R0603-YAGEO [mm]
  rect 0.9x0.8 smd mask+0.05: 1(-0.85,0) 2(0.85,0)
  Top Layer pour cut-out: 0.4,0.4 -0.4,0.4 -0.4,-0.4 0.4,-0.4
  silkscreen extent -1.58,-0.67 1.58,0.67, body extent -0.8,-0.4 0.8,0.4, height 0.5
R0805#1 [mil]
  rect 59.05x60 smd: 1(-45,0) 2(45,0)
  silkscreen extent -90,-45 90,45, body extent -39,-25 39,25, height 22
R0805#2 [mil]
  rect 39.37x49.61 smd mask+1.97: 1(-43.31,0) 2(43.31,0)
  Top Layer pour cut-out: 23.62,23.62 -23.62,23.62 -23.62,-23.62 23.62,-23.62
  silkscreen extent -74,-35 74,35, body extent -39,-25 39,25, height 20
R0805-YAGEO [mm]
  rect 1x1.26 smd mask+0.05: 1(-1.1,0) 2(1.1,0)
  Top Layer pour cut-out: 0.6,0.6 -0.6,0.6 -0.6,-0.6 0.6,-0.6
  silkscreen extent -1.88,-0.9 1.88,0.9, body extent -1,-0.63 1,0.63, height 0.5
R1206#1 [mm]
  rect 1.4x1.8 smd: 1(-1.6,0) 2(1.6,0)
  Top Layer pour cut-out: -0.787,0.991 -0.787,-0.965 0.762,-0.965 0.762,0.991
  silkscreen extent -2.65,-1.25 2.65,1.25, body extent -1.6,-0.8 1.6,0.8, height 0.6
R1206#2 [mm]
  rect 1x1.6 smd mask+0.05: 1(-1.6,0) 2(1.6,0)
  Top Layer pour cut-out: -1.1,0.75 1.1,0.75 1.1,-0.75 -1.1,-0.75
  silkscreen extent -2.37,-1.07 2.37,1.07, body extent -1.6,-0.8 1.6,0.8, height 0.65
R1206-YAGEO [mm]
  rect 1x1.5 smd mask+0.05: 1(-1.6,0) 2(1.6,0)
  Top Layer pour cut-out: -1.1,0.75 1.1,0.75 1.1,-0.75 -1.1,-0.75
  silkscreen extent -2.37,-1.02 2.37,1.02, body extent -1.6,-0.8 1.6,0.8, height 0.65
SKPMAPE010 [mm]
  rect 2x2 smd mask+0.05: 1(-3,0) 2(3,0)
  silkscreen extent -3,-3 3,3, body extent -3,-3 3,3, height 5
SO-8 [mil] "取自《M50N》"
  rect 80x24 smd: 1(-110,75)
  oval 80x24 smd: 2(-110,25) 3(-110,-25) 4(-110,-75) 5(110,-75) 6(110,-25) 7(110,25) 8(110,75)
  silkscreen extent -130,-100 50,125, body extent -119,-99 119,99, height 63
SOD-123#1 [mm] "4148W"
  rect 1.5x1.6 smd: 1(1.615,0) 2(-1.614,0)
  Top Layer pour cut-out: 0.762,-0.889 0.762,0.889 -0.762,0.889 -0.762,-0.889
  silkscreen extent -2.82,-1.3 2.69,1.3
SOD-123#2 [mm]
  rect 0.91x1.22 smd mask+0.05: 1(1.637,0) 2(-1.637,0)
  Top Layer pour cut-out: -1.15,0.625 -1.15,-0.65 1.15,-0.65 1.15,0.625
  silkscreen extent -1.35,-0.85 2.32,0.85, body extent -1.85,-0.8 1.85,0.8, height 1.27
SOT-23#1 [mm]
  rect 0.8x0.9 smd mask+0.05: B(-0.95,-1) C(0,1) E(0.95,-1)
  Top Layer pour cut-out: -1.5,0.7 1.5,0.7 1.5,-0.7 -1.5,-0.7
  silkscreen extent -1.45,-0.65 1.45,0.65, body extent -1.5,-1.25 1.5,1.25, height 1.06
SOT-23#2 [mm]
  rect 1x1.2 smd: B(-0.952,-0.943) C(0,0.943) E(0.952,-0.943)
  silkscreen extent -1.46,-1.27 1.46,1.02, body extent -1.45,-1.4 1.45,1.4, height 1.2
SOT-89 [mm]
  rect 0.7x1.1 smd mask+0.05: 1(1.5,-1.75) 3(-1.5,-1.75)
  rect 0.7x1.9 smd mask+0.05: 2(0,-1.35)
  rect 2x2.8 smd mask+0.05: 2(0,0.9)
  silkscreen extent -2.3,-1.3 2.3,1.3, body extent -2.25,-2.18 2.25,1.75, height 1.4
SOT-89-3#1 [mm] "取自《FE-3AD》"
  rect 0.8x1.5 smd mask+0.05: B(-1.499,-1.973) E(1.5,-1.973)
  rect 0.8x2.2 smd mask+0.05: C(0,-1.638)
  rect 1.8x2.7 smd mask+0.05: C(0,0.773)
  silkscreen extent -2.25,-1.22 2.25,1.23, body extent -2.3,-2.25 2.3,2, height 1.59
SOT-89-3#2 [mm] "取自《FE-3AD》"
  rect 0.8x1.27 smd: B(-1.524,-1.223) E(1.524,-1.223)
  rect 0.8x1.8 smd: C(0,-0.963)
  rect 1.8x2.6 smd: C(0.032,1.223)
  silkscreen extent -2.29,-0.46 2.29,1.95, body extent -2.3,-1.75 2.3,2.5, height 1.59
TP1.0 [mm]
  round 1 smd paste-1 mask+0.05: 1(0,0)
VLS6045EX [mm]
  rect 2.4x5.1 smd mask+0.05: 1(-2.35,0) 2(2.35,0)
  Keep-Out Layer pour cut-out: -4.2,3.6 4.2,3.6 4.2,-3.6 -4.2,-3.6
  silkscreen extent -3.15,-3 3.15,3
"钉孔M2.5*12 - BYD" [mm]
  round 6 hole 2.8: 1(0,0)
  silkscreen extent -4.5,-4.5 4.5,4.5
"钉孔M2.5*12 - SU2" [mm] "适配 M2.5*12 螺钉(螺帽直径6mm)"
  round 2.7 hole 2.7 unplated mask+0: 1(0,0)
  Multi-Layer pour cut-out: 0,-3.5 -1.339,-3.234 -2.475,-2.475 -3.234,-1.339 -3.5,0 -3.5,0 -3.234,1.339 -2.475,2.475 -1.339,3.234 0,3.5 0,3.5 1.339,3.234 2.475,2.475 3.234,1.339 3.5,0 3.5,0 3.234,-1.339 2.475,-2.475 1.339,-3.234 0,-3.5
  silkscreen extent -3.5,-3.5 3.5,3.5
